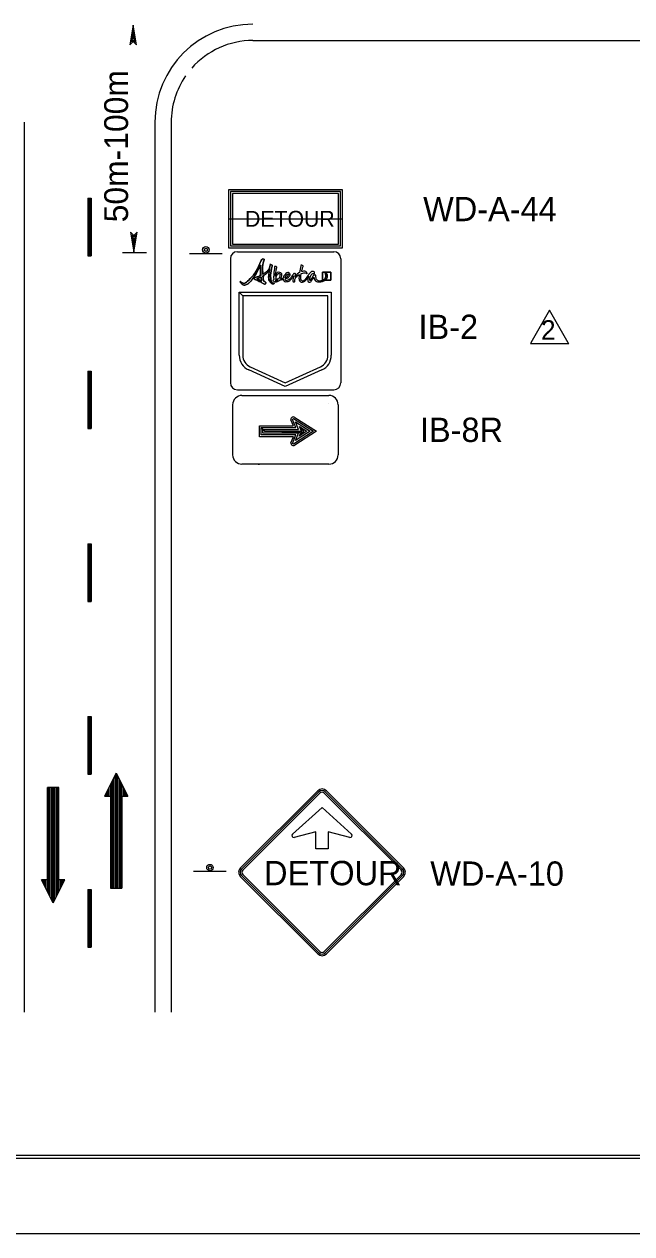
# Model space of a CAD drawing. Extents: x 1482 to 1692, y 225 to 494.
# Drawn here: x 1542.3 to 1587.3, y 224.6 to 314.2 of the extents above; entities that cross this region are included whole.
import ezdxf

# ---------------------------------------------------------------- set-up
doc = ezdxf.new("R2010")
doc.units = 0
for name, color, linetype in [('Level 1', 7, 'Continuous'), ('Level 17', 7, 'Continuous'), ('Level 2', 7, 'Continuous'), ('Level 53', 7, 'Continuous'), ('Level 60', 7, 'Continuous')]:
    doc.layers.add(name, color=color, linetype=linetype)

msp = doc.modelspace()

# ---------------------------------------------------------------- linework, layer by layer
at = {"layer": 'Level 1'}
for points in [[(1550.366, 314.144), (1550.124, 312.692), (1550.366, 312.934), (1550.608, 312.692), (1550.366, 314.144), (1550.366, 313.699), (1550.235, 312.91), (1550.366, 313.041), (1550.497, 312.91), (1550.366, 313.699), (1550.366, 313.249), (1550.342, 313.113), (1550.366, 313.138), (1550.39, 313.113), (1550.366, 313.249), (1550.366, 313.138)], [(1550.416, 297.364), (1550.658, 298.816), (1550.416, 298.574), (1550.174, 298.816), (1550.416, 297.364), (1550.416, 297.809), (1550.547, 298.598), (1550.416, 298.467), (1550.285, 298.598), (1550.416, 297.809), (1550.416, 298.259), (1550.44, 298.395), (1550.416, 298.37), (1550.392, 298.395), (1550.416, 298.259), (1550.416, 298.37)]]:
    msp.add_lwpolyline(points, dxfattribs=at)
at = {"layer": 'Level 17'}
for p, q in [((1557.418, 299.806), (1565.856, 299.806)), ((1551.355, 297.296), (1549.577, 297.296)), ((1554.53, 297.236), (1556.949, 297.236)), ((1558.418, 286.714), (1564.854, 286.714)), ((1557.734, 282.33), (1557.734, 286.028)), ((1564.797, 286.136), (1564.797, 286.136)), ((1565.532, 286.028), (1565.532, 282.33)), ((1562.224, 284.465), (1562.026, 284.927)), ((1562.334, 285.094), (1563.946, 284.069)), ((1559.709, 284.465), (1562.218, 284.465)), ((1559.709, 283.666), (1559.709, 284.465)), ((1563.946, 284.069), (1562.334, 283.038)), ((1562.224, 283.666), (1559.709, 283.666)), ((1562.032, 283.205), (1562.224, 283.666)), ((1564.854, 281.633), (1558.418, 281.633)), ((1558.305, 251.726), (1564.024, 257.445)), ((1558.39, 251.641), (1564.109, 257.36)), ((1558.475, 251.556), (1564.194, 257.275)), ((1564.5, 257.275), (1570.219, 251.556)), ((1564.585, 257.36), (1570.304, 251.641)), ((1564.669, 257.445), (1570.388, 251.726)), ((1562.283, 253.993), (1562.283, 253.993)), ((1562.283, 253.993), (1562.283, 253.993)), ((1562.283, 253.993), (1562.283, 253.993)), ((1554.834, 251.481), (1557.253, 251.481)), ((1557.983, 251.404), (1557.983, 251.404)), ((1564.024, 245.362), (1558.305, 251.081)), ((1564.109, 245.447), (1558.39, 251.166)), ((1564.194, 245.532), (1558.475, 251.251)), ((1570.219, 251.251), (1564.5, 245.532)), ((1570.304, 251.166), (1564.585, 245.447)), ((1570.388, 251.081), (1564.669, 245.362))]:
    msp.add_line(p, q, dxfattribs=at)
for points in [[(1565.85, 301.96), (1557.424, 301.96), (1557.424, 297.652), (1565.85, 297.652)], [(1565.71, 301.82), (1557.566, 301.82), (1557.566, 297.794), (1565.71, 297.794)], [(1565.57, 301.68), (1557.705, 301.68), (1557.705, 297.934), (1565.57, 297.934)]]:
    msp.add_lwpolyline(points, close=True, dxfattribs=at)
for points in [[(1559.844, 284.344), (1562.416, 284.344), (1562.162, 284.939), (1562.23, 285.004), (1563.71, 284.069), (1562.224, 283.121), (1562.154, 283.16), (1562.416, 283.793), (1559.838, 283.793), (1559.844, 284.344), (1559.966, 284.21), (1562.608, 284.21), (1562.385, 284.76), (1563.466, 284.069), (1562.385, 283.378), (1562.608, 283.928), (1559.966, 283.928), (1559.966, 284.21), (1560.1, 284.081), (1562.82, 284.081), (1562.673, 284.428), (1563.23, 284.069), (1562.66, 283.704), (1562.744, 283.908), (1562.998, 284.069), (1562.756, 284.23), (1562.806, 284.063), (1562.744, 283.908), (1562.614, 283.998), (1560.106, 284.063), (1560.1, 284.081)], [(1559.844, 284.344), (1562.416, 284.344)], [(1559.608, 281.627), (1559.716, 281.627)], [(1562.16, 254.226), (1564.347, 256.214), (1566.534, 254.226)], [(1562.16, 254.226), (1564.347, 256.214), (1566.534, 254.226)], [(1562.16, 254.226), (1564.347, 256.214), (1566.534, 254.226)], [(1566.405, 253.993), (1564.798, 254.405), (1564.798, 253.154), (1563.891, 253.154), (1563.891, 254.405), (1562.283, 253.993)], [(1566.405, 253.993), (1564.798, 254.405), (1564.798, 253.154), (1563.891, 253.154), (1563.891, 254.405), (1562.283, 253.993)], [(1566.405, 253.993), (1564.798, 254.405), (1564.798, 253.154), (1563.891, 253.154), (1563.891, 254.405), (1562.283, 253.993)]]:
    msp.add_lwpolyline(points, dxfattribs=at)
for centre, radius in [((1555.744, 297.507), 0.242), ((1555.744, 297.507), 0.121), ((1556.048, 251.751), 0.242), ((1556.048, 251.751), 0.121)]:
    msp.add_circle(centre, radius, dxfattribs=at)
for centre, radius, start, end in [((1559.225, 306.96), 6.048, 145.49398, 180), ((1558.418, 286.03), 0.692, 90, 180), ((1564.848, 286.03), 0.692, 0, 90), ((1562.227, 284.929), 0.199, 57.50378, 180.10575), ((1562.23, 283.206), 0.199, 180.10506, 302.49855), ((1558.418, 282.326), 0.692, 180, 270), ((1564.848, 282.326), 0.692, 270, 0), ((1564.347, 257.123), 0.456, 45, 135), ((1564.347, 257.123), 0.336, 45, 135), ((1564.347, 257.123), 0.216, 45, 135), ((1562.251, 254.123), 0.137, 132.30479, 284.40748), ((1562.251, 254.123), 0.137, 132.30479, 284.40748), ((1562.251, 254.123), 0.137, 132.30479, 284.40748), ((1566.44, 254.123), 0.137, 255.59252, 47.69521), ((1566.44, 254.123), 0.137, 255.59252, 47.69521), ((1566.44, 254.123), 0.137, 255.59252, 47.69521), ((1558.628, 251.404), 0.456, 135, 225), ((1558.628, 251.404), 0.336, 135, 225), ((1558.628, 251.404), 0.216, 135, 225), ((1570.066, 251.404), 0.216, 315, 45), ((1570.066, 251.404), 0.336, 315, 45), ((1570.066, 251.404), 0.456, 315, 45), ((1564.347, 245.684), 0.216, 225, 315), ((1564.347, 245.684), 0.456, 225, 315), ((1564.347, 245.684), 0.336, 225, 315)]:
    msp.add_arc(centre, radius, start, end, dxfattribs=at)
at = {"layer": 'Level 2'}
for p, q in [((1559.225, 313.009), (1620.696, 313.009)), ((1542.29, 306.96), (1542.29, 241.05)), ((1551.968, 306.96), (1551.968, 241.05)), ((1553.177, 306.96), (1553.177, 241.05)), ((1547.001, 301.332), (1547.001, 297.066)), ((1547.001, 301.332), (1547.257, 301.332)), ((1547.065, 301.332), (1547.065, 297.066)), ((1547.129, 301.332), (1547.129, 297.066)), ((1547.193, 301.332), (1547.193, 297.066)), ((1547.257, 301.332), (1547.257, 297.066)), ((1547.001, 297.066), (1547.257, 297.066)), ((1557.558, 296.849), (1557.558, 287.662)), ((1558.076, 297.367), (1565.219, 297.367)), ((1558.076, 297.367), (1565.219, 297.367)), ((1565.737, 296.849), (1565.737, 287.662)), ((1558.219, 289.695), (1558.219, 294.363)), ((1558.219, 294.363), (1558.474, 294.107)), ((1558.474, 294.107), (1558.219, 294.363)), ((1558.219, 294.363), (1565.034, 294.363)), ((1558.474, 294.107), (1558.474, 289.695)), ((1564.778, 294.107), (1558.474, 294.107)), ((1564.778, 289.695), (1564.778, 294.107)), ((1565.034, 294.363), (1565.034, 289.695)), ((1547.001, 288.532), (1547.001, 284.266)), ((1547.001, 288.532), (1547.257, 288.532)), ((1547.065, 288.532), (1547.065, 284.266)), ((1547.129, 288.532), (1547.129, 284.266)), ((1547.193, 288.532), (1547.193, 284.266)), ((1547.257, 288.532), (1547.257, 284.266)), ((1561.626, 287.377), (1558.918, 288.609)), ((1559.023, 288.842), (1561.626, 287.658)), ((1561.626, 287.658), (1564.229, 288.842)), ((1564.335, 288.609), (1561.626, 287.377)), ((1558.076, 287.144), (1565.219, 287.144)), ((1547.001, 284.266), (1547.257, 284.266)), ((1547.001, 275.733), (1547.001, 271.466)), ((1547.001, 275.733), (1547.257, 275.733)), ((1547.065, 275.733), (1547.065, 271.466)), ((1547.129, 275.733), (1547.129, 271.466)), ((1547.193, 275.733), (1547.193, 271.466)), ((1547.257, 275.733), (1547.257, 271.466)), ((1547.001, 271.466), (1547.257, 271.466)), ((1547.001, 262.933), (1547.001, 258.667)), ((1547.001, 262.933), (1547.257, 262.933)), ((1547.065, 262.933), (1547.065, 258.667)), ((1547.129, 262.933), (1547.129, 258.667)), ((1547.193, 262.933), (1547.193, 258.667)), ((1547.257, 262.933), (1547.257, 258.667)), ((1547.001, 258.667), (1547.257, 258.667)), ((1549.102, 258.753), (1548.249, 257.046)), ((1548.782, 258.113), (1548.782, 250.219)), ((1548.889, 258.326), (1548.889, 250.219)), ((1548.996, 258.539), (1548.996, 250.219)), ((1549.102, 258.753), (1549.102, 250.219)), ((1549.102, 258.753), (1549.956, 257.046)), ((1549.209, 258.539), (1549.209, 250.219)), ((1549.316, 258.326), (1549.316, 250.219)), ((1549.422, 258.113), (1549.422, 250.219)), ((1544.008, 250.857), (1544.008, 257.684)), ((1544.861, 257.684), (1544.008, 257.684)), ((1544.008, 250.004), (1544.008, 257.684)), ((1544.114, 249.791), (1544.114, 257.684)), ((1544.221, 249.577), (1544.221, 257.684)), ((1544.328, 249.364), (1544.328, 257.684)), ((1544.434, 249.151), (1544.434, 257.684)), ((1544.541, 249.364), (1544.541, 257.684)), ((1544.648, 249.577), (1544.648, 257.684)), ((1544.754, 249.791), (1544.754, 257.684)), ((1544.861, 250.857), (1544.861, 257.684)), ((1544.861, 250.004), (1544.861, 257.684)), ((1548.356, 257.259), (1548.356, 257.046)), ((1548.462, 257.473), (1548.462, 257.046)), ((1548.569, 257.686), (1548.569, 257.046)), ((1548.676, 257.899), (1548.676, 250.219)), ((1549.529, 257.899), (1549.529, 250.219)), ((1549.636, 257.686), (1549.636, 257.046)), ((1549.742, 257.473), (1549.742, 257.046)), ((1549.849, 257.259), (1549.849, 257.046)), ((1548.249, 257.046), (1548.676, 257.046)), ((1548.676, 257.046), (1548.676, 250.219)), ((1549.529, 257.046), (1549.529, 250.219)), ((1549.529, 257.046), (1549.956, 257.046)), ((1544.434, 249.151), (1543.581, 250.857)), ((1544.008, 250.857), (1543.581, 250.857)), ((1543.688, 250.644), (1543.688, 250.857)), ((1543.794, 250.431), (1543.794, 250.857)), ((1543.901, 250.217), (1543.901, 250.857)), ((1544.434, 249.151), (1545.288, 250.857)), ((1545.288, 250.857), (1544.861, 250.857)), ((1544.968, 250.217), (1544.968, 250.857)), ((1545.074, 250.431), (1545.074, 250.857)), ((1545.181, 250.644), (1545.181, 250.857)), ((1547.001, 250.134), (1547.001, 245.867)), ((1547.001, 250.134), (1547.257, 250.134)), ((1547.065, 250.134), (1547.065, 245.867)), ((1547.129, 250.134), (1547.129, 245.867)), ((1547.193, 250.134), (1547.193, 245.867)), ((1547.257, 250.134), (1547.257, 245.867)), ((1548.676, 250.219), (1549.529, 250.219)), ((1547.001, 245.867), (1547.257, 245.867))]:
    msp.add_line(p, q, dxfattribs=at)
for centre, radius, start, end in [((1559.225, 306.96), 7.258, 90, 180), ((1559.225, 306.96), 6.048, 90, 138.53434), ((1558.076, 296.849), 0.518, 90, 180), ((1565.219, 296.849), 0.518, 0, 90), ((1559.411, 289.695), 1.193, 180, 245.54318), ((1559.411, 289.695), 0.937, 180, 245.54318), ((1563.841, 289.695), 0.937, 294.45682, 0), ((1563.841, 289.695), 1.193, 294.45682, 0), ((1558.076, 287.662), 0.518, 180, 270), ((1565.219, 287.662), 0.518, 270, 0)]:
    msp.add_arc(centre, radius, start, end, dxfattribs=at)
at = {"layer": 'Level 53'}
msp.add_line((1564.556, 295.251), (1564.406, 295.251), dxfattribs=at)
msp.add_lwpolyline([(1564.556, 295.251), (1564.997, 295.251), (1564.997, 295.859), (1564.389, 295.859), (1564.389, 295.251), (1564.406, 295.251)], dxfattribs=at)
for points, degree in [([(1560.744, 295.031), (1560.678, 295.04), (1560.593, 295.129), (1560.567, 295.276), (1560.52, 295.539), (1560.548, 295.799), (1560.625, 296.187), (1560.64, 296.26), (1560.69, 296.387), (1560.531, 296.411), (1560.48, 296.419), (1560.506, 296.394), (1560.492, 296.327), (1560.431, 296.039), (1560.195, 295.831), (1559.958, 295.691), (1559.933, 296.022), (1559.944, 296.389), (1560.006, 296.614), (1560.058, 296.803), (1560.121, 296.768), (1560.043, 296.808), (1559.962, 296.85), (1559.874, 296.795), (1559.803, 296.654), (1559.733, 296.512), (1559.406, 295.744), (1558.885, 295.226), (1558.619, 294.961), (1558.377, 295.098), (1558.329, 295.138), (1558.29, 295.172), (1558.275, 295.12), (1558.324, 295.068), (1558.54, 294.835), (1558.855, 294.969), (1558.969, 295.084), (1559.286, 295.4), (1559.655, 296.083), (1559.804, 296.372), (1559.79, 296.209), (1559.786, 295.936), (1559.816, 295.615), (1559.655, 295.537), (1559.51, 295.491), (1559.442, 295.473), (1559.368, 295.453), (1559.322, 295.423), (1559.321, 295.389), (1559.319, 295.351), (1559.369, 295.32), (1559.441, 295.286), (1559.569, 295.225), (1559.943, 295.048), (1560.035, 294.995), (1560.114, 294.949), (1560.152, 294.985), (1560.176, 295.034), (1560.206, 295.099), (1560.122, 295.136), (1560.041, 295.16), (1560.01, 295.269), (1559.985, 295.415), (1559.968, 295.575), (1560.159, 295.692), (1560.346, 295.848), (1560.454, 296.043), (1560.427, 295.88), (1560.357, 295.327), (1560.532, 295.093), (1560.57, 295.041), (1560.655, 294.985), (1560.738, 294.993), (1560.777, 294.997), (1560.797, 295.023), (1560.793, 295.031), (1560.789, 295.039), (1560.767, 295.027), (1560.744, 295.031)], 3), ([(1559.958, 295.691), (1559.933, 296.022), (1559.944, 296.389), (1560.006, 296.614), (1560.058, 296.803), (1560.121, 296.768), (1560.043, 296.808), (1559.962, 296.85), (1559.874, 296.795), (1559.803, 296.654), (1559.733, 296.512), (1559.406, 295.744), (1558.885, 295.226), (1558.619, 294.961), (1558.377, 295.098), (1558.329, 295.138), (1558.29, 295.172), (1558.275, 295.12), (1558.324, 295.068), (1558.54, 294.835), (1558.855, 294.969), (1558.969, 295.084), (1559.286, 295.4), (1559.655, 296.083), (1559.804, 296.372)], 3), ([(1559.804, 296.372), (1559.79, 296.209), (1559.786, 295.936), (1559.816, 295.615)], 2), ([(1560.744, 295.031), (1560.678, 295.04), (1560.593, 295.129), (1560.567, 295.276), (1560.52, 295.539), (1560.548, 295.799), (1560.625, 296.187), (1560.64, 296.26), (1560.69, 296.387), (1560.531, 296.411), (1560.48, 296.419), (1560.506, 296.394), (1560.492, 296.327), (1560.431, 296.039), (1560.195, 295.831), (1559.958, 295.691)], 3), ([(1559.968, 295.575), (1560.159, 295.692), (1560.346, 295.848), (1560.454, 296.043)], 2), ([(1560.454, 296.043), (1560.427, 295.88), (1560.357, 295.327), (1560.532, 295.093), (1560.57, 295.041), (1560.655, 294.985), (1560.738, 294.993), (1560.777, 294.997), (1560.797, 295.023), (1560.793, 295.031), (1560.789, 295.039), (1560.767, 295.027), (1560.744, 295.031)], 3), ([(1560.89, 295.533), (1560.903, 295.688), (1560.927, 295.877), (1560.962, 296.052), (1560.977, 296.125), (1561.027, 296.252), (1560.868, 296.277), (1560.817, 296.284), (1560.825, 296.261), (1560.829, 296.192), (1560.835, 296.101), (1560.733, 295.545), (1560.787, 295.3)], 3), ([(1561.282, 295.352), (1561.395, 295.536), (1561.385, 295.784), (1561.22, 295.826), (1561.028, 295.874), (1560.931, 295.688), (1560.89, 295.533)], 3), ([(1560.931, 295.317), (1560.957, 295.512), (1561.058, 295.784), (1561.185, 295.74), (1561.258, 295.715), (1561.219, 295.486), (1561.126, 295.334)], 3), ([(1561.616, 295.359), (1561.642, 295.367), (1561.666, 295.375), (1561.686, 295.384), (1561.926, 295.491), (1562.009, 295.651), (1561.948, 295.749), (1561.89, 295.842), (1561.724, 295.814), (1561.593, 295.676), (1561.528, 295.608), (1561.479, 295.491), (1561.473, 295.385)], 3), ([(1562.345, 295.472), (1562.361, 295.547), (1562.384, 295.63), (1562.386, 295.687), (1562.388, 295.746), (1562.347, 295.759), (1562.331, 295.764), (1562.297, 295.774), (1562.255, 295.756), (1562.214, 295.698), (1562.118, 295.563), (1561.996, 295.348), (1561.811, 295.258), (1561.678, 295.194), (1561.619, 295.259), (1561.616, 295.359)], 3), ([(1561.745, 295.664), (1561.826, 295.739), (1561.866, 295.733), (1561.876, 295.713), (1561.899, 295.67), (1561.804, 295.516), (1561.622, 295.432)], 3), ([(1561.622, 295.432), (1561.638, 295.515), (1561.681, 295.605), (1561.745, 295.664)], 2), ([(1562.233, 295.592), (1562.219, 295.446), (1562.124, 295.126), (1562.286, 295.142), (1562.35, 295.149), (1562.322, 295.159), (1562.326, 295.214), (1562.34, 295.406), (1562.5, 295.57), (1562.659, 295.67)], 3), ([(1562.683, 295.834), (1562.554, 295.759), (1562.433, 295.635), (1562.345, 295.472)], 2), ([(1562.659, 295.67), (1562.632, 295.434), (1562.641, 295.223), (1562.748, 295.156), (1562.945, 295.033), (1563.224, 295.357), (1563.377, 295.556)], 3), ([(1562.84, 295.898), (1562.858, 295.979), (1562.879, 296.062), (1562.901, 296.142), (1562.921, 296.215), (1562.982, 296.342), (1562.825, 296.367), (1562.775, 296.374), (1562.796, 296.35), (1562.779, 296.282), (1562.749, 296.158), (1562.711, 295.996), (1562.683, 295.834)], 3), ([(1564.218, 295.197), (1563.969, 295.197), (1563.904, 295.391), (1563.892, 295.487), (1563.884, 295.551), (1563.898, 295.644), (1563.788, 295.631), (1563.711, 295.623), (1563.641, 295.472), (1563.543, 295.346), (1563.459, 295.237), (1563.422, 295.248), (1563.441, 295.341), (1563.465, 295.458), (1563.563, 295.732), (1563.674, 295.752), (1563.726, 295.761), (1563.744, 295.67), (1563.768, 295.727), (1563.792, 295.784), (1563.77, 295.906), (1563.655, 295.906), (1563.574, 295.906), (1563.477, 295.821), (1563.397, 295.723), (1563.328, 295.638), (1562.978, 295.122), (1562.831, 295.234), (1562.762, 295.286), (1562.768, 295.498), (1562.811, 295.747)], 3), ([(1562.811, 295.747), (1562.985, 295.815), (1563.13, 295.793), (1563.212, 295.753), (1563.253, 295.734), (1563.258, 295.737), (1563.241, 295.781), (1563.215, 295.847), (1563.075, 295.949), (1562.856, 295.902), (1562.851, 295.901), (1562.846, 295.9), (1562.84, 295.898)], 3), ([(1564.389, 295.859), (1564.389, 295.859), (1564.389, 295.251), (1564.389, 295.251), (1564.389, 295.251), (1564.406, 295.251), (1564.406, 295.251), (1564.538, 295.33), (1564.627, 295.481), (1564.627, 295.606), (1564.627, 295.713), (1564.57, 295.708), (1564.576, 295.723), (1564.595, 295.766), (1564.729, 295.741), (1564.737, 295.59), (1564.743, 295.461), (1564.676, 295.336), (1564.556, 295.251), (1564.556, 295.251), (1564.997, 295.251), (1564.997, 295.251), (1564.997, 295.251), (1564.997, 295.859), (1564.997, 295.859), (1564.997, 295.859), (1564.389, 295.859), (1564.389, 295.859)], 3), ([(1564.406, 295.251), (1564.538, 295.33), (1564.627, 295.481), (1564.627, 295.606), (1564.627, 295.713), (1564.57, 295.708), (1564.576, 295.723), (1564.595, 295.766), (1564.729, 295.741), (1564.737, 295.59), (1564.743, 295.461), (1564.676, 295.336), (1564.556, 295.251)], 3), ([(1559.816, 295.615), (1559.655, 295.537), (1559.51, 295.491), (1559.442, 295.473), (1559.368, 295.453), (1559.322, 295.423), (1559.321, 295.389), (1559.319, 295.351), (1559.369, 295.32), (1559.441, 295.286), (1559.569, 295.225), (1559.943, 295.048), (1560.035, 294.995), (1560.114, 294.949), (1560.152, 294.985), (1560.176, 295.034), (1560.206, 295.099), (1560.122, 295.136), (1560.041, 295.16)], 3), ([(1559.525, 295.361), (1559.609, 295.392), (1559.716, 295.437), (1559.829, 295.496)], 2), ([(1559.525, 295.361), (1559.609, 295.392), (1559.716, 295.437), (1559.829, 295.496), (1559.844, 295.367), (1559.861, 295.274), (1559.879, 295.205), (1559.796, 295.235), (1559.678, 295.283), (1559.525, 295.361)], 3), ([(1559.879, 295.205), (1559.796, 295.235), (1559.678, 295.283), (1559.525, 295.361)], 2), ([(1559.829, 295.496), (1559.844, 295.367), (1559.861, 295.274), (1559.879, 295.205)], 2), ([(1560.041, 295.16), (1560.01, 295.269), (1559.985, 295.415), (1559.968, 295.575)], 2), ([(1560.787, 295.3), (1560.718, 295.278), (1560.69, 295.227), (1560.778, 295.172), (1560.839, 295.135), (1560.973, 295.123), (1561.108, 295.189), (1561.156, 295.213), (1561.198, 295.246), (1561.233, 295.286)], 3), ([(1560.91, 295.199), (1560.919, 295.207), (1560.925, 295.218), (1560.925, 295.231), (1560.925, 295.239), (1560.925, 295.248), (1560.925, 295.257)], 3), ([(1560.965, 295.2), (1560.943, 295.196), (1560.925, 295.197), (1560.91, 295.199)], 2), ([(1560.925, 295.257), (1560.96, 295.258), (1561.013, 295.262), (1561.077, 295.268)], 2), ([(1561.126, 295.334), (1561.065, 295.328), (1561, 295.323), (1560.931, 295.317)], 2), ([(1561.077, 295.268), (1561.044, 295.232), (1561.006, 295.206), (1560.965, 295.2)], 2), ([(1561.233, 295.286), (1561.313, 295.296), (1561.398, 295.309), (1561.475, 295.324)], 2), ([(1561.473, 295.385), (1561.417, 295.373), (1561.353, 295.362), (1561.282, 295.352)], 2), ([(1561.475, 295.324), (1561.488, 295.217), (1561.558, 295.135), (1561.72, 295.15), (1561.951, 295.172), (1562.156, 295.455), (1562.233, 295.592)], 3), ([(1563.377, 295.556), (1563.299, 295.38), (1563.255, 295.154), (1563.372, 295.12), (1563.51, 295.079), (1563.618, 295.308), (1563.745, 295.482)], 3), ([(1563.745, 295.482), (1563.76, 295.357), (1563.844, 295.141), (1564.181, 295.141), (1564.332, 295.141), (1564.461, 295.184), (1564.556, 295.251)], 3), ([(1564.406, 295.251), (1564.35, 295.218), (1564.286, 295.197), (1564.218, 295.197)], 2)]:
    msp.add_open_spline(points, degree=degree, dxfattribs=at)
at = {"layer": 'Level 60'}
for points in [[(1482.41, 493.623), (1692.41, 493.623), (1692.41, 224.631), (1482.41, 224.631)], [(1493.127, 487.958), (1687.519, 487.958), (1687.519, 230.208), (1493.127, 230.208)], [(1500.536, 487.818), (1687.41, 487.818), (1687.41, 230.436), (1500.536, 230.436)]]:
    msp.add_lwpolyline(points, close=True, dxfattribs=at)
for points in [[(1581.191, 293.047), (1579.798, 290.622)], [(1582.585, 290.622), (1581.191, 293.047)], [(1579.798, 290.622), (1579.772, 290.577), (1582.611, 290.577), (1582.585, 290.622)]]:
    msp.add_lwpolyline(points, dxfattribs=at)

# ---------------------------------------------------------------- texts
at = {"layer": 'Level 17'}
for s, height, rotation, p in [('50m-100m', 1.764, 90, (1549.979, 299.544)), ('WD-A-44', 1.8, 360, (1571.832, 299.629)), ('IB-2', 1.8, 360, (1571.489, 290.902)), ('IB-8R', 1.8, 360, (1571.595, 283.276)), ('WD-A-10', 1.8, 360, (1572.363, 250.41))]:
    msp.add_text(s, height=height, rotation=rotation, dxfattribs=at).set_placement(p)
for height, p in [(1.1758, (1558.646, 299.218)), (1.8063, (1560.045, 250.446))]:
    msp.add_text('DETOUR', height=height, dxfattribs=at).set_placement(p)
at = {"layer": 'Level 60'}
msp.add_text('2', height=1.448, rotation=360, dxfattribs=at).set_placement((1580.564, 290.846))

doc.saveas('drawing.dxf')
